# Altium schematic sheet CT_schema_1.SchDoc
size 487 x 447 mm
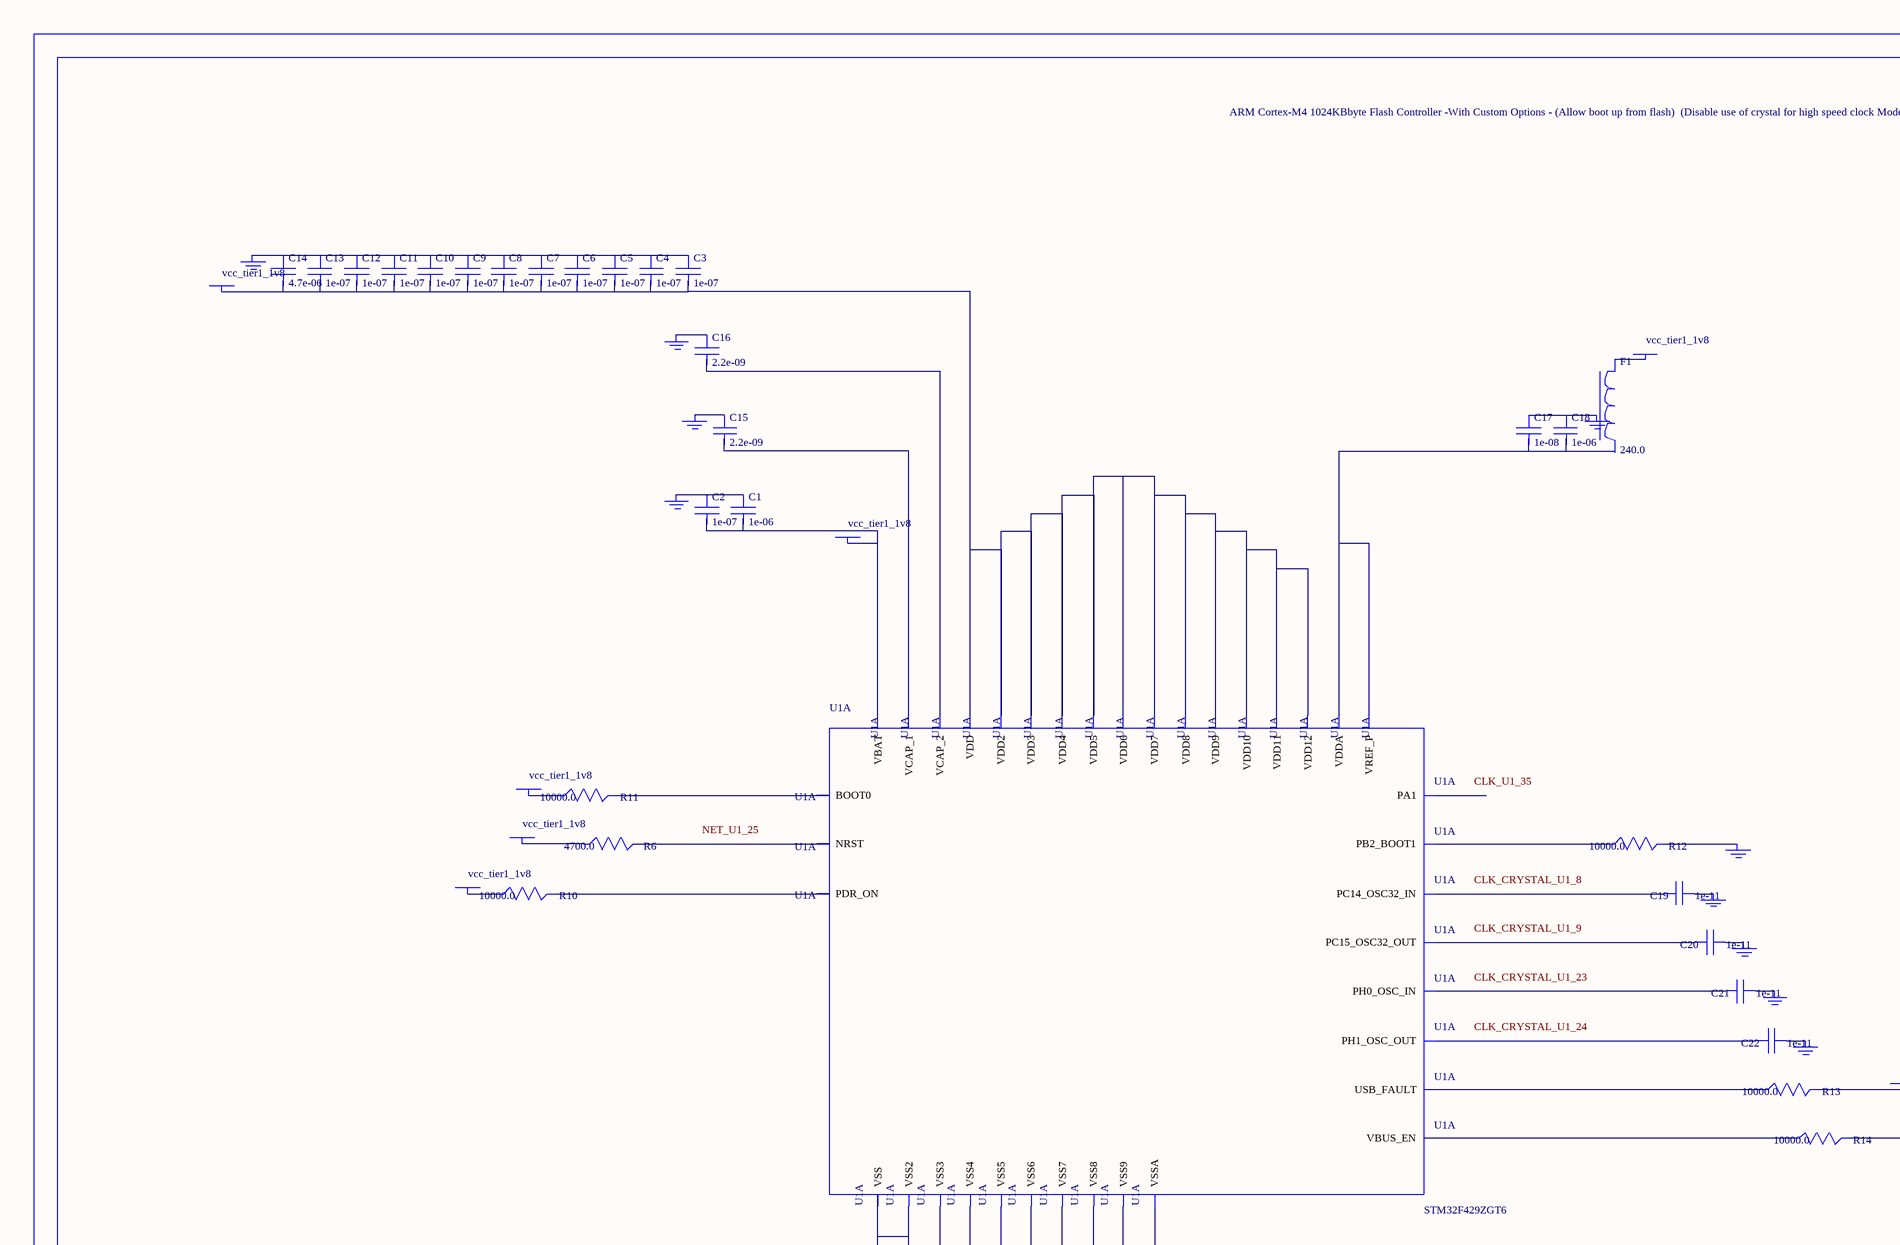
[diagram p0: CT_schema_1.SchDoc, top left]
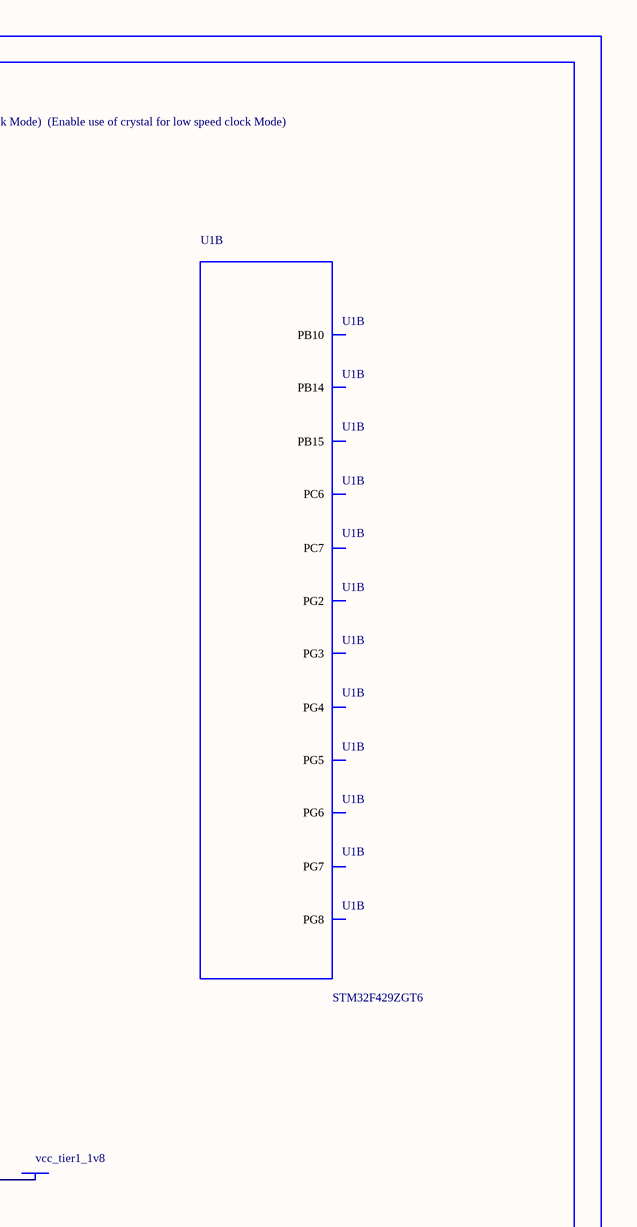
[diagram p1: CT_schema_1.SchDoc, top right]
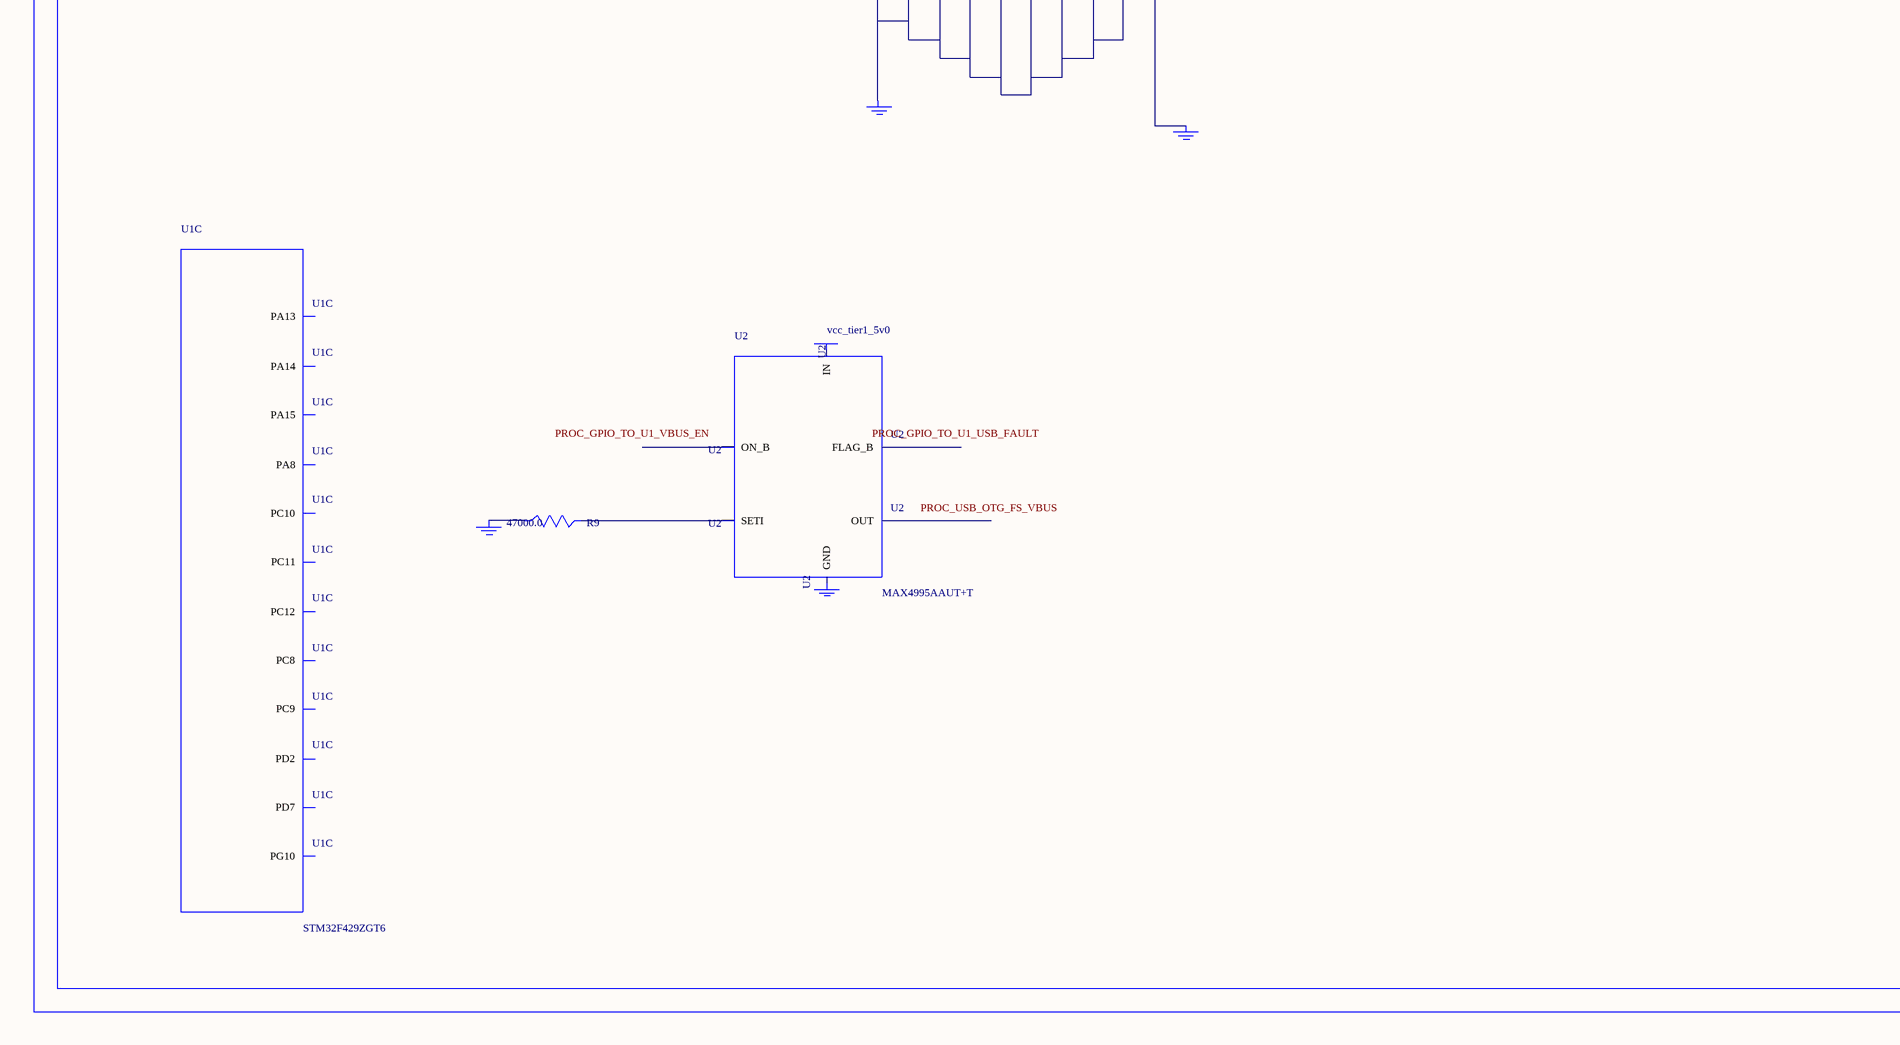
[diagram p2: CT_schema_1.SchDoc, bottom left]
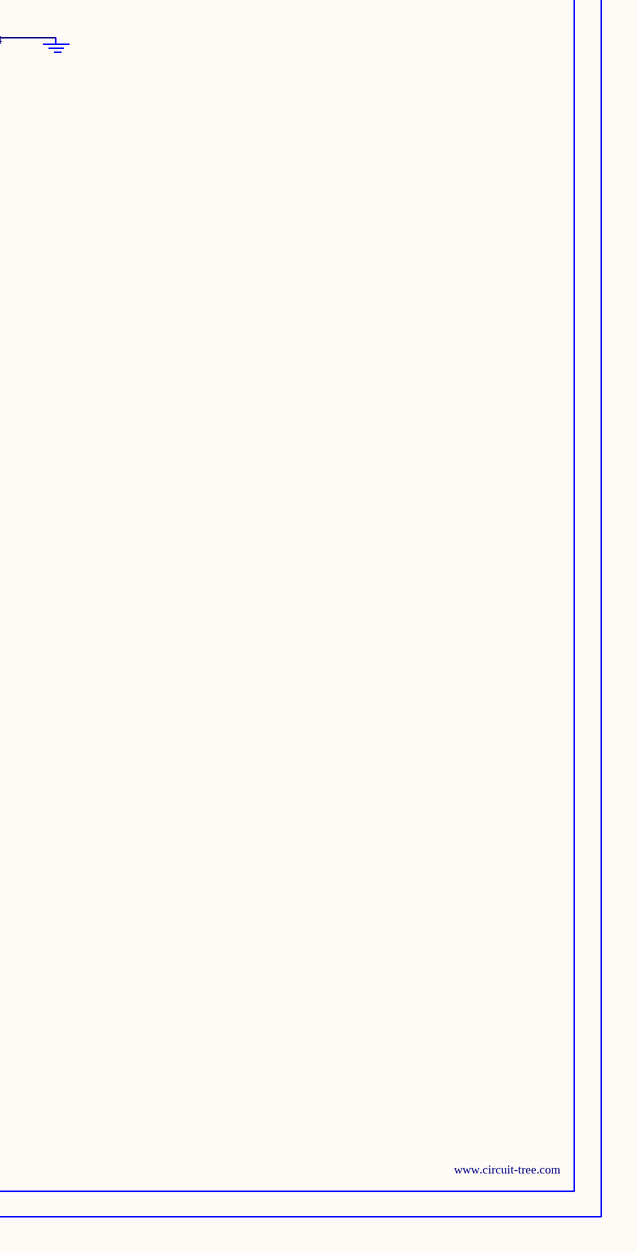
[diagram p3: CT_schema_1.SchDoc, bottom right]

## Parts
BORDER0  (no value)
C1  1e-06  [C0603]
C2  1e-07  [C0603]
C3  1e-07  [C0603]
C4  1e-07  [C0603]
C5  1e-07  [C0603]
C6  1e-07  [C0603]
C7  1e-07  [C0603]
C8  1e-07  [C0603]
C9  1e-07  [C0603]
C10  1e-07  [C0603]
C11  1e-07  [C0603]
C12  1e-07  [C0603]
C13  1e-07  [C0603]
C14  4.7e-06  [C0603]
C15  2.2e-09  [C0603]
C16  2.2e-09  [C0603]
C17  1e-08  [C0603]
C18  1e-06  [C0603]
C19  1e-11  [C0402]
C20  1e-11  [C0402]
C21  1e-11  [C0402]
C22  1e-11  [C0402]
F1  240.0  [L0603]
GND_INSTANCE_0_0  (no value)
GND_INSTANCE_0_1  (no value)
GND_INSTANCE_0_2  (no value)
GND_INSTANCE_0_3  (no value)
GND_INSTANCE_0_4  (no value)
GND_INSTANCE_0_5  (no value)
GND_INSTANCE_0_6  (no value)
GND_INSTANCE_0_7  (no value)
GND_INSTANCE_0_8  (no value)
GND_INSTANCE_0_9  (no value)
GND_INSTANCE_0_10  (no value)
GND_INSTANCE_0_11  (no value)
GND_INSTANCE_0_12  (no value)
GND_INSTANCE_0_13  (no value)
GND_INSTANCE_0_14  (no value)
POWER_INSTANCE_0_0  vcc_tier1_1v8
POWER_INSTANCE_0_1  vcc_tier1_1v8
POWER_INSTANCE_0_2  vcc_tier1_1v8
POWER_INSTANCE_0_3  vcc_tier1_1v8
POWER_INSTANCE_0_4  vcc_tier1_1v8
POWER_INSTANCE_0_5  vcc_tier1_1v8
POWER_INSTANCE_0_6  vcc_tier1_1v8
POWER_INSTANCE_0_7  vcc_tier1_5v0
R6  4700.0  [R0603]
R9  47000.0  [R0603]
R10  10000.0  [R0603]
R11  10000.0  [R0603]
R12  10000.0  [R0603]
R13  10000.0  [R0603]
R14  10000.0  [R0603]
U1  STM32F429ZGT6  [LQFP144]  (parts A,B,C of 11)
U2  MAX4995AAUT+T  [SOT-23-6]

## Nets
NetC1_1: C1.1 C2.1 GND_INSTANCE_0_0.0(GND)
NetC1_2: C1.2 C2.2 POWER_INSTANCE_0_0.0(PWR) U1.6(VBAT)
NetC3_1: C3.1 C4.1 C5.1 C6.1 C7.1 C8.1 C9.1 C10.1 C11.1 C12.1 C13.1 C14.1 GND_INSTANCE_0_4.0(GND)
NetC3_2: C3.2 C4.2 C5.2 C6.2 C7.2 C8.2 C9.2 C10.2 C11.2 C12.2 C13.2 C14.2 POWER_INSTANCE_0_2.0(PWR) U1.17(VDD) U1.30(VDD2) U1.39(VDD3) U1.52(VDD4) U1.62(VDD5) U1.72(VDD6) U1.84(VDD7) U1.95(VDD8) U1.108(VDD9) U1.121(VDD10) U1.131(VDD11) U1.144(VDD12)
NetC15_1: C15.1 GND_INSTANCE_0_10.0(GND)
NetC15_2: C15.2 U1.71(VCAP_1)
NetC16_1: C16.1 GND_INSTANCE_0_11.0(GND)
NetC16_2: C16.2 U1.106(VCAP_2)
NetC17_1: C17.1 C18.1 GND_INSTANCE_0_8.0(GND)
NetC17_2: C17.2 C18.2 U1.32(VREF_P) U1.33(VDDA)
NetC19_1: C19.1 GND_INSTANCE_0_2.0(GND)
NetC19_2: C19.2 U1.8(PC14_OSC32_IN)
NetC20_1: C20.1 GND_INSTANCE_0_3.0(GND)
NetC20_2: C20.2 U1.9(PC15_OSC32_OUT)
NetC21_1: C21.1 GND_INSTANCE_0_5.0(GND)
NetC21_2: C21.2 U1.23(PH0_OSC_IN)
NetC22_1: C22.1 GND_INSTANCE_0_6.0(GND)
NetC22_2: C22.2 U1.24(PH1_OSC_OUT)
NetF1_1: F1.1 POWER_INSTANCE_0_3.0(PWR)
NetGND_INSTANCE_0_1_0: GND_INSTANCE_0_1.0(GND) R14.2
NetGND_INSTANCE_0_7_0: GND_INSTANCE_0_7.0(GND) U1.31(VSSA)
NetGND_INSTANCE_0_9_0: GND_INSTANCE_0_9.0(GND) R12.2
NetGND_INSTANCE_0_12_0: GND_INSTANCE_0_12.0(GND) U1.16(VSS) U1.38(VSS2) U1.51(VSS3) U1.61(VSS4) U1.83(VSS5) U1.94(VSS6) U1.107(VSS7) U1.120(VSS8) U1.130(VSS9)
NetGND_INSTANCE_0_13_0: GND_INSTANCE_0_13.0(GND) R9.1
NetPOWER_INSTANCE_0_1_0: POWER_INSTANCE_0_1.0(PWR) R13.2
NetPOWER_INSTANCE_0_4_0: POWER_INSTANCE_0_4.0(PWR) R11.1
NetPOWER_INSTANCE_0_5_0: POWER_INSTANCE_0_5.0(PWR) R10.1
NetPOWER_INSTANCE_0_6_0: POWER_INSTANCE_0_6.0(PWR) R6.1
NetR6_2: R6.2 U1.25(NRST)
NetR9_2: R9.2 U2.3(SETI)
NetR10_2: R10.2 U1.143(PDR_ON)
NetR11_2: R11.2 U1.138(BOOT0)
NetR12_1: R12.1 U1.48(PB2_BOOT1)
NetR13_1: R13.1 U1.10(USB_FAULT)
NetR14_1: R14.1 U1.7(VBUS_EN)

Not connected (* = marked no-connect by the designer): F1 2; GND_INSTANCE_0_14 0(GND); POWER_INSTANCE_0_7 0(PWR); U1 35(PA1) 69(PB10) 75(PB14) 76(PB15) 87(PG2) 88(PG3) 89(PG4) 90(PG5) 91(PG6) 92(PG7) 93(PG8) 96(PC6) 97(PC7) 98(PC8) 99(PC9) 100(PA8) 105(PA13) 109(PA14) 110(PA15) 111(PC10) 112(PC11) 113(PC12) 116(PD2) 123(PD7) 125(PG10); U2 1(OUT) 2(GND) 4(ON_B) 5(IN) 6(FLAG_B)

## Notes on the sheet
- Labels drawn without touching a wire or pin: CLK_CRYSTAL_U1_8, CLK_CRYSTAL_U1_9, CLK_CRYSTAL_U1_23, CLK_CRYSTAL_U1_24, CLK_U1_35, NET_U1_25, PROC_GPIO_TO_U1_USB_FAULT, PROC_GPIO_TO_U1_VBUS_EN, PROC_USB_OTG_FS_VBUS

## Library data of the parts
BORDER0 = BORDER_PAGE0
C1 C18 = C0603C105K3RACTU
C2-C13 = 06035C104K4Z2A
C14 = GRM188R6YA475KE15D
C15 C16 = 06031C222KAZ2A
C17 = 06035C103K4Z2A
C19-C22 = C0402C100K3GACTU
F1 = Z0603C241ASMST
GND_INSTANCE_0_0-GND_INSTANCE_0_14 = GND
POWER_INSTANCE_0_0-POWER_INSTANCE_0_7 = PWR
R6 = RC0603JR-074K7L
R9 = RC0603JR-0747KL
R10-R14 = RC0603JR-0710KL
